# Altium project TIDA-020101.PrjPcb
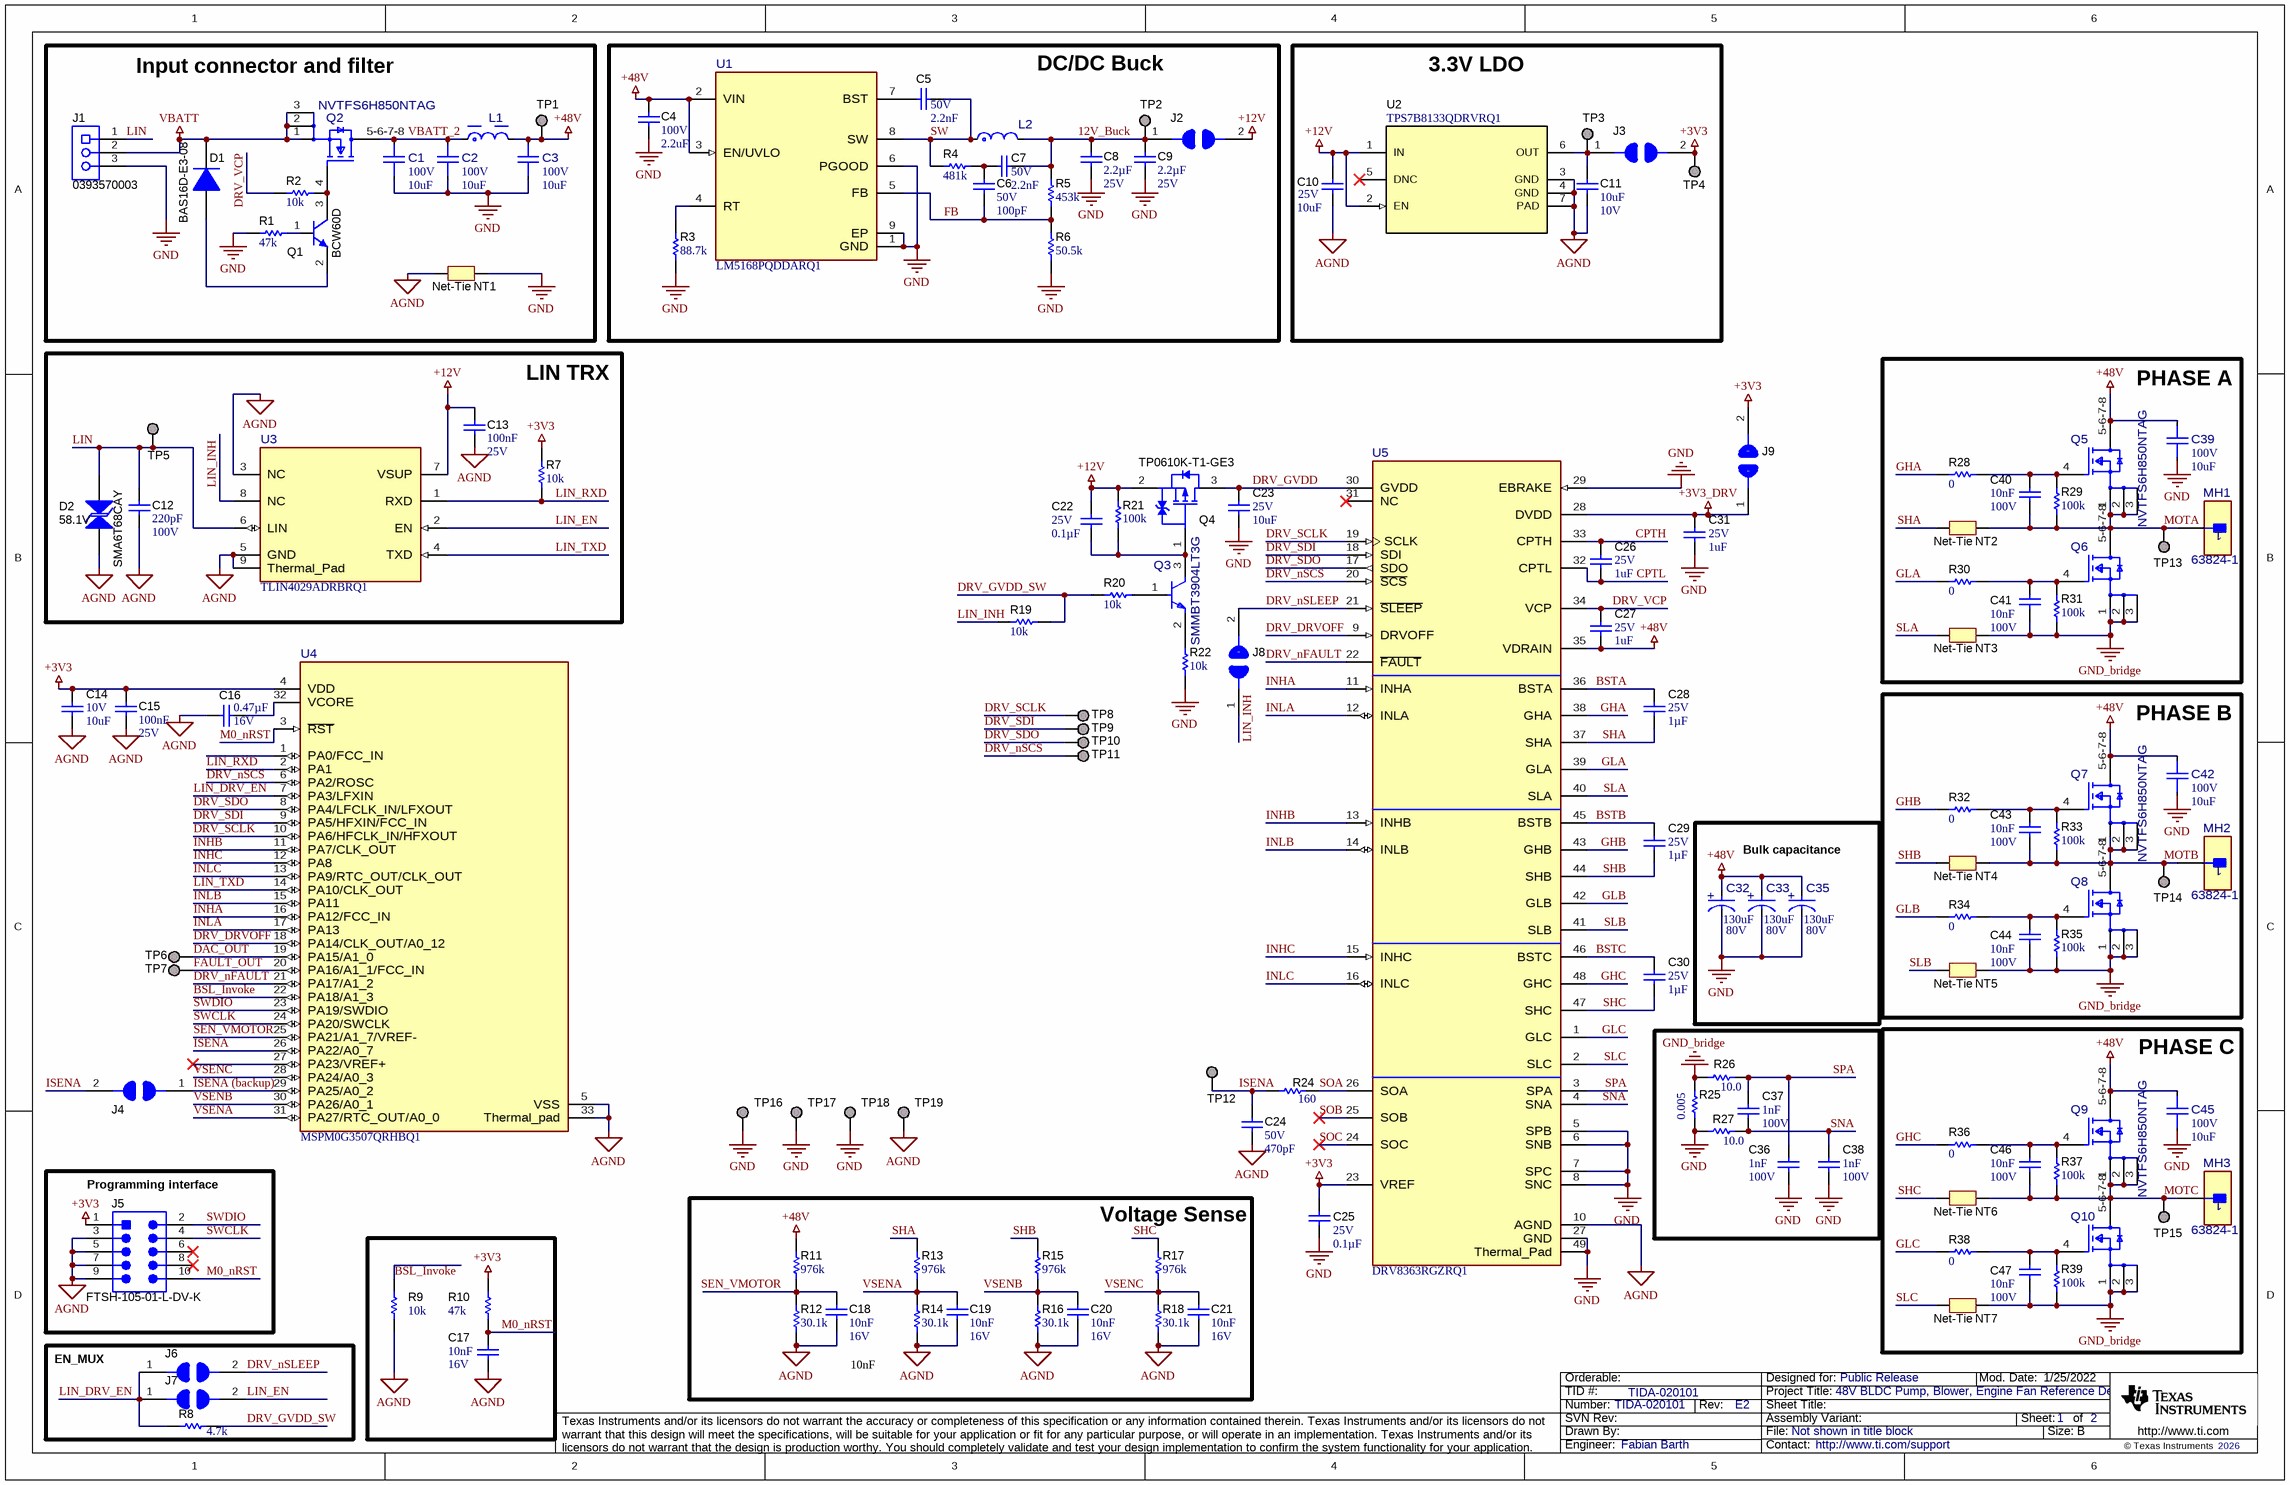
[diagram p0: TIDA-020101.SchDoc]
CopyrightYear: 2026; PCB_Layout: Fabian Barth; PCB_Rev: E2; PRJ_Customer: Public Release; PRJ_Engineer: Fabian Barth; PRJ_Number: TIDA-020101; PRJ_Title: 48V BLDC Pump, Blower, Engine Fan Reference Design; SCH_Rev: E2; TechSupport: http://www.ti.com/support; TID: TIDA-020101
2 sheets, 152 parts. Net scope: global (net labels, ports and power ports of the same name join across sheets).
Board file: TIDA-020101.PcbDoc
Sheets:
  TIDA-020101.SchDoc
  TIDA-020101_Hardware.SchDoc

## Sheet TIDA-020101.SchDoc
size 431 x 279 mm; Date: Not shown in title block; ApprovedBy: Not shown in title block; CheckedBy: Not shown in title block; Author: Not shown in title block; CompanyName: Not shown in title block; Engineer: Not shown in title block; Organization: Not shown in title block; Address1: Not shown in title block; Address2: Not shown in title block; Address3: Not shown in title block; Address4: Not shown in title block; DocumentNumber: 2; Revision: Use project parameter SCH_Rev; SheetNumber: 1; SheetTotal: 2; PageSetup: Record=PageOptions¦CenterHorizontal=True¦CenterVertical=True¦PrintScale=1.00¦XCorrection=1.00¦YCorrection=1.00¦PrintKind=0¦BorderSize=5000000¦LeftOffset=0¦BottomOffset=0¦Orientation=2¦PaperLength=1000¦PaperWidth=1000¦Scale=100¦PaperSource=15¦PrintQuality=600¦MediaType=1¦DitherType=10¦PaperKind=Letter¦PrintScaleMode=1

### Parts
C1  VDC_V: 100V  ValueDisplayed: 10uF  [FP-CGA6P1X7R2A106K250AC_1210-MFG]  (hidden comment: CGA6P1X7R2A106K250AC)
C2  VDC_V: 100V  ValueDisplayed: 10uF  [FP-CGA6P1X7R2A106K250AC_1210-MFG]  (hidden comment: CGA6P1X7R2A106K250AC)
C3  VDC_V: 100V  ValueDisplayed: 10uF  [FP-CGA6P1X7R2A106K250AC_1210-MFG]  (hidden comment: CGA6P1X7R2A106K250AC)
C4  VDC_V: 100V  ValueDisplayed: 2.2uF  [1210_250L]  (hidden comment: CGA6N3X7R2A225K230AB)
C5  Cap_F: 2.2nF  VDC_V: 50V  [0402S]  (hidden comment: CL05B222JB5NNNC)
C6  VDC_V: 50V  ValueDisplayed: 100pF  [0402L]  (hidden comment: CC0402KRX7R9BB101)
C7  Cap_F: 2.2nF  VDC_V: 50V  [0603L]  (hidden comment: GRM188R71H222KA01D)
C8  Cap_F: 2.2µF  VDC_V: 25V  [0805L]  (hidden comment: CGA4J3X7R1E225K125AB)
C9  Cap_F: 2.2µF  VDC_V: 25V  [0805L]  (hidden comment: CGA4J3X7R1E225K125AB)
C10  VDC_V: 25V  ValueDisplayed: 10uF  [0805L]  (hidden comment: GRM21BZ71E106KE15L)
C11  ValueDisplayed: 10uF  VDC_V: 10V  [0603L]  (hidden comment: GRM188Z71A106MA73D)
C12  Cap_F: 220pF  VDC_V: 100V  [0603L]  (hidden comment: GRM188R72A221KA01D)
C13  Cap_F: 100nF  VDC_V: 25V  [0402L]  (hidden comment: CGA2B3X7R1E104K050BB)
C14  VDC_V: 10V  ValueDisplayed: 10uF  [0603L]  (hidden comment: C1608X5R1A106M080AC)
C15  Cap_F: 100nF  VDC_V: 25V  [0402L]  (hidden comment: CGA2B3X7R1E104K050BB)
C16  ValueDisplayed: 0.47µF  VDC_V: 16V  [0402S]  (hidden comment: CGA2B1X7S1C474K050BE)
C17  Cap_F: 10nF  VDC_V: 16V  [0402S]  (hidden comment: GRM155R71C103KA01D)
C18  Cap_F: 10nF  VDC_V: 16V  [0402S]  (hidden comment: GRM155R71C103KA01D)
C19  Cap_F: 10nF  VDC_V: 16V  [0402S]  (hidden comment: GRM155R71C103KA01D)
C20  Cap_F: 10nF  VDC_V: 16V  [0402S]  (hidden comment: GRM155R71C103KA01D)
C21  Cap_F: 10nF  VDC_V: 16V  [0402S]  (hidden comment: GRM155R71C103KA01D)
C22  VDC_V: 25V  ValueDisplayed: 0.1µF  [0402L]  (hidden comment: CGA2B3X7R1E104K050BB)
C23  VDC_V: 25V  ValueDisplayed: 10uF  [0805L]  (hidden comment: GRM21BZ71E106KE15L)
C24  VDC_V: 50V  ValueDisplayed: 470pF  [0402L]  (hidden comment: CGA2B2X7R1H471K050BA)
C25  VDC_V: 25V  ValueDisplayed: 0.1µF  [0402L]  (hidden comment: CGA2B3X7R1E104K050BB)
C26  VDC_V: 25V  ValueDisplayed: 1uF  [0402S]  (hidden comment: C1005X5R1E105K050BC)
C27  VDC_V: 25V  ValueDisplayed: 1uF  [0402S]  (hidden comment: C1005X5R1E105K050BC)
C28  VDC_V: 25V  ValueDisplayed: 1µF  [0603S]  (hidden comment: CGA3E1X7R1E105K080AD)
C29  VDC_V: 25V  ValueDisplayed: 1µF  [0603S]  (hidden comment: CGA3E1X7R1E105K080AD)
C30  VDC_V: 25V  ValueDisplayed: 1µF  [0603S]  (hidden comment: CGA3E1X7R1E105K080AD)
C31  VDC_V: 25V  ValueDisplayed: 1uF  [0402L]  (hidden comment: C1005X5R1E105K050BC)
C32  ValueDisplayed: 130uF  VDC_V: 80V  [FP-B40910A0137M000_SMD2-MFG]  (hidden comment: B40910A0137M000)
C33  ValueDisplayed: 130uF  VDC_V: 80V  [FP-B40910A0137M000_SMD2-MFG]  (hidden comment: B40910A0137M000)
C35  ValueDisplayed: 130uF  VDC_V: 80V  [FP-B40910A0137M000_SMD2-MFG]  (hidden comment: B40910A0137M000)
C36  Cap_F: 1nF  VDC_V: 100V  [0402L]  (hidden comment: CGA2B3X7S2A102K050BB)
C37  Cap_F: 1nF  VDC_V: 100V  [0402L]  (hidden comment: CGA2B3X7S2A102K050BB)
C38  Cap_F: 1nF  VDC_V: 100V  [0402L]  (hidden comment: CGA2B3X7S2A102K050BB)
C39  VDC_V: 100V  ValueDisplayed: 10uF  [FP-CGA6P1X7R2A106K250AC_1210-MFG]  (hidden comment: CGA6P1X7R2A106K250AC)
C40  Cap_F: 10nF  VDC_V: 100V  [0603S]  (hidden comment: CGA3E2X7R2A103K080AA)
C41  Cap_F: 10nF  VDC_V: 100V  [0603S]  (hidden comment: CGA3E2X7R2A103K080AA)
C42  VDC_V: 100V  ValueDisplayed: 10uF  [FP-CGA6P1X7R2A106K250AC_1210-MFG]  (hidden comment: CGA6P1X7R2A106K250AC)
C43  Cap_F: 10nF  VDC_V: 100V  [0603S]  (hidden comment: CGA3E2X7R2A103K080AA)
C44  Cap_F: 10nF  VDC_V: 100V  [0603S]  (hidden comment: CGA3E2X7R2A103K080AA)
C45  VDC_V: 100V  ValueDisplayed: 10uF  [FP-CGA6P1X7R2A106K250AC_1210-MFG]  (hidden comment: CGA6P1X7R2A106K250AC)
C46  Cap_F: 10nF  VDC_V: 100V  [0603S]  (hidden comment: CGA3E2X7R2A103K080AA)
C47  Cap_F: 10nF  VDC_V: 100V  [0603S]  (hidden comment: CGA3E2X7R2A103K080AA)
D1  BAS16D-E3-08  [SOD-123]
D2  SMA6T68CAY  value 58.1V  [SMA_Bi]
J1  0393570003  [MOLEX_39357-0003]
J2  SOLDER JUMPER  [SolderJumper_50MIL]  (value not drawn)
J3  SOLDER JUMPER  [SolderJumper_50MIL]  (value not drawn)
J4  SOLDER JUMPER  [SolderJumper_50MIL]  (value not drawn)
J5  FTSH-105-01-L-DV-K  [Samtec_FTSH-105-01-x-DV-K]
J6  SOLDER JUMPER  [SolderJumper_50MIL]  (value not drawn)
J7  SOLDER JUMPER  [SolderJumper_50MIL]  (value not drawn)
J8  SOLDER JUMPER  [SolderJumper_50MIL]  (value not drawn)
J9  SOLDER JUMPER  [SolderJumper_50MIL]  (value not drawn)
L1  74438377022  [FP-74438377022_SMD2-MFG]  (value not drawn)
L2  LPS4040-104MRC  [FP-LPS4040-104MRC_SMT_IND_3MM9_3MM9-MFG]  (value not drawn)
MH1  63824-1  [FP-63824-1_CONN_7MM92_3MM11-MFG]
MH2  63824-1  [FP-63824-1_CONN_7MM92_3MM11-MFG]
MH3  63824-1  [FP-63824-1_CONN_7MM92_3MM11-MFG]
NT1  Net-Tie  [Net-Tie_50milWide_30milLong]  (net tie, no BOM)
NT2  Net-Tie  [Net-Tie_20milWide_60milLong]  (net tie, no BOM)
NT3  Net-Tie  [Net-Tie_20milWide_60milLong]  (net tie, no BOM)
NT4  Net-Tie  [Net-Tie_20milWide_60milLong]  (net tie, no BOM)
NT5  Net-Tie  [Net-Tie_20milWide_60milLong]  (net tie, no BOM)
NT6  Net-Tie  [Net-Tie_20milWide_60milLong]  (net tie, no BOM)
NT7  Net-Tie  [Net-Tie_20milWide_60milLong]  (net tie, no BOM)
Q1  BCW60D  [SOT-23]
Q2  NVTFS6H850NTAG  [FP-NVTFS6H850NTAG_WDFN8-MFG]
Q3  SMMBT3904LT3G  [FP-SMMBT3904LT3G_SOT23-IPC_C]
Q4  TP0610K-T1-GE3  [SOT-23L]
Q5  NVTFS6H850NTAG  [FP-NVTFS6H850NTAG_WDFN8-MFG]
Q6  NVTFS6H850NTAG  [FP-NVTFS6H850NTAG_WDFN8-MFG]  (value not drawn)
Q7  NVTFS6H850NTAG  [FP-NVTFS6H850NTAG_WDFN8-MFG]
Q8  NVTFS6H850NTAG  [FP-NVTFS6H850NTAG_WDFN8-MFG]  (value not drawn)
Q9  NVTFS6H850NTAG  [FP-NVTFS6H850NTAG_WDFN8-MFG]
Q10  NVTFS6H850NTAG  [FP-NVTFS6H850NTAG_WDFN8-MFG]  (value not drawn)
R1  ValueDisplayed: 47k  [0402L]  (hidden comment: CRCW040247K0JNED)
R2  ValueDisplayed: 10k  [0402L]  (hidden comment: CRCW040210K0JNED)
R3  ValueDisplayed: 88.7k  [0603L]  (hidden comment: CRCW060388K7FKEA)
R4  ValueDisplayed: 481k  [0603L]  (hidden comment: RT0603DRE07481KL)
R5  ValueDisplayed: 453k  [0603L]  (hidden comment: RC0603FR-07453KL)
R6  ValueDisplayed: 50.5k  [0603L]  (hidden comment: RT0603BRD0750K5L)
R7  ValueDisplayed: 10k  [0402L]  (hidden comment: CRCW040210K0JNED)
R8  ValueDisplayed: 4.7k  [0402L]  (hidden comment: CRCW04024K70JNED)
R9  ValueDisplayed: 10k  [0402L]  (hidden comment: CRCW040210K0JNED)
R10  ValueDisplayed: 47k  [0402L]  (hidden comment: CRCW040247K0JNED)
R11  ValueDisplayed: 976k  [0402S]  (hidden comment: CRCW0402976KFKED)
R12  ValueDisplayed: 30.1k  [0402S]  (hidden comment: CRCW040230K1FKED)
R13  ValueDisplayed: 976k  [0402S]  (hidden comment: CRCW0402976KFKED)
R14  ValueDisplayed: 30.1k  [0402S]  (hidden comment: CRCW040230K1FKED)
R15  ValueDisplayed: 976k  [0402S]  (hidden comment: CRCW0402976KFKED)
R16  ValueDisplayed: 30.1k  [0402S]  (hidden comment: CRCW040230K1FKED)
R17  ValueDisplayed: 976k  [0402S]  (hidden comment: CRCW0402976KFKED)
R18  ValueDisplayed: 30.1k  [0402S]  (hidden comment: CRCW040230K1FKED)
R19  ValueDisplayed: 10k  [0402L]  (hidden comment: CRCW040210K0JNED)
R20  ValueDisplayed: 10k  [0402L]  (hidden comment: CRCW040210K0JNED)
R21  ValueDisplayed: 100k  [0402L]  (hidden comment: CRCW0402100KJNED)
R22  ValueDisplayed: 10k  [0402L]  (hidden comment: CRCW040210K0JNED)
R24  ValueDisplayed: 160  [0402L]  (hidden comment: CRCW0402160RJNED)
R25  ValueDisplayed: 0.005  [CRE2512-R5_R9]  (hidden comment: CRE2512-FZ-R005E-3)
R26  ValueDisplayed: 10.0  [0402L]  (hidden comment: CRCW040210R0FKED)
R27  ValueDisplayed: 10.0  [0402L]  (hidden comment: CRCW040210R0FKED)
R28  ValueDisplayed: 0  [0402L]  (hidden comment: CRCW04020000Z0ED)
R29  ValueDisplayed: 100k  [0402S]  (hidden comment: CRCW0402100KJNED)
R30  ValueDisplayed: 0  [0402L]  (hidden comment: CRCW04020000Z0ED)
R31  ValueDisplayed: 100k  [0402S]  (hidden comment: CRCW0402100KJNED)
R32  ValueDisplayed: 0  [0402L]  (hidden comment: CRCW04020000Z0ED)
R33  ValueDisplayed: 100k  [0402S]  (hidden comment: CRCW0402100KJNED)
R34  ValueDisplayed: 0  [0402L]  (hidden comment: CRCW04020000Z0ED)
R35  ValueDisplayed: 100k  [0402S]  (hidden comment: CRCW0402100KJNED)
R36  ValueDisplayed: 0  [0402L]  (hidden comment: CRCW04020000Z0ED)
R37  ValueDisplayed: 100k  [0402S]  (hidden comment: CRCW0402100KJNED)
R38  ValueDisplayed: 0  [0402L]  (hidden comment: CRCW04020000Z0ED)
R39  ValueDisplayed: 100k  [0402S]  (hidden comment: CRCW0402100KJNED)
TP1  5017  [Keystone_5017]  (value not drawn)
TP2  5017  [Keystone_5017]  (value not drawn)
TP3  5017  [Keystone_5017]  (value not drawn)
TP4  5017  [Keystone_5017]  (value not drawn)
TP5  5017  [Keystone_5017]  (value not drawn)
TP6  5017  [Keystone_5017]  (value not drawn)
TP7  5017  [Keystone_5017]  (value not drawn)
TP8  5017  [Keystone_5017]  (value not drawn)
TP9  5017  [Keystone_5017]  (value not drawn)
TP10  5017  [Keystone_5017]  (value not drawn)
TP11  5017  [Keystone_5017]  (value not drawn)
TP12  5017  [Keystone_5017]  (value not drawn)
TP13  5017  [Keystone_5017]  (value not drawn)
TP14  5017  [Keystone_5017]  (value not drawn)
TP15  5017  [Keystone_5017]  (value not drawn)
TP16  5017  [Keystone_5017]  (value not drawn)
TP17  5017  [Keystone_5017]  (value not drawn)
TP18  5017  [Keystone_5017]  (value not drawn)
TP19  5017  [Keystone_5017]  (value not drawn)
U1  LM5168PQDDARQ1  [DDA0008E-IPC_C]
U2  TPS7B8133QDRVRQ1  [DRV0006A]
U3  TLIN4029ADRBRQ1  [DRB0008J-MFG]
U4  MSPM0G3507QRHBQ1  [RHB0032D-MFG]
U5  DRV8363RGZRQ1  [RGZ0048L-MFG]

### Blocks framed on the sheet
Input connector and filter: C1-C3 D1 J1 L1 NT1 Q1 Q2 R1 R2 TP1
DC/DC Buck: C4-C9 J2 L2 R3-R6 TP2 U1
3.3V LDO: C10 C11 J3 TP3 TP4 U2
LIN TRX: C12 C13 D2 R7 TP5 U3
PHASE A: C39-C41 MH1 NT2 NT3 Q5 Q6 R28-R31 TP13
PHASE B: C42-C44 MH2 NT4 NT5 Q7 Q8 R32-R35 TP14
Bulk capacitance: C32 C33 C35
PHASE C: C45-C47 MH3 NT6 NT7 Q9 Q10 R36-R39 TP15
Programming interface: J5
Voltage Sense: C18-C21 R11-R18
EN_MUX: J6 J7 R8

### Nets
+3V3: C14.1 C15.1 C25.1 J3.2 J5.1 J9.2 R7.2 R10.2 TP4.1 U4.4(VDD) U5.23(VREF)
+3V3_DRV: C31.1 J9.1 U5.28(DVDD)
+12V: C10.1 C13.1 C22.1 J2.2 Q4.2(S) R21.2 U2.1(IN) U2.2(EN) U3.7(VSUP)
+48V: C3.2 C4.1 C27.2 C32.2(ANODE) C33.2(ANODE) C35.2(ANODE) C39.2 C42.2 C45.2 L1.2 Q5.5-6-7-8(D) Q7.5-6-7-8(D) Q9.5-6-7-8(D) R11.2 TP1.1 U1.2(VIN) U1.3(EN/UVLO) U5.35(VDRAIN)
AGND: C10.2 C11.2 C12.2 C13.2 C14.2 C15.2 C16.1 C17.2 C18.2 C19.2 C20.2 C21.2 C24.2 D2.1 J5.3 J5.5 J5.7 J5.9 NT1.1 R9.1 R12.1 R14.1 R16.1 R18.1 TP19.1 U2.3(GND) U2.4(GND) U2.7(PAD) U3.3(NC) U3.5(GND) U3.9(Thermal_Pad) U4.5(VSS) U4.33(Thermal_pad) U5.10(AGND)
GND: C1.1 C2.1 C3.1 C4.2 C8.2 C9.2 C23.2 C25.2 C31.2 C32.1(CATHODE) C33.1(CATHODE) C35.1(CATHODE) C36.2 C38.2 C39.1 C42.1 C45.1 J1.3 NT1.2 R1.1 R3.1 R6.1 R22.2 R25.1 R27.1 TP16.1 TP17.1 TP18.1 U1.1(GND) U1.6(PGOOD) U1.9(EP) U5.5(SPB) U5.6(SNB) U5.7(SPC) U5.8(SNC) U5.27(GND) U5.29(EBRAKE) U5.49(Thermal_Pad)
GND_bridge: C41.2 C44.2 C47.2 NT3.2 NT5.2 NT7.2 Q6.1(S) Q6.2(S) Q6.3(S) Q8.1(S) Q8.2(S) Q8.3(S) Q10.1(S) Q10.2(S) Q10.3(S) R25.2 R26.1 R31.1 R35.1 R39.1
VBATT: D1.1(K) J1.2 Q2.1(S) Q2.2(S) Q2.3(S)
12V_Buck: C7.1 C8.1 C9.1 J2.1 L2.2 R5.2 TP2.1
BSL_Invoke: R9.2 U4.22(PA18/A1_3)
BSTA: C28.1 U5.36(BSTA)
BSTB: C29.1 U5.45(BSTB)
BSTC: C30.1 U5.46(BSTC)
CPTH: C26.1 U5.33(CPTH)
CPTL: C26.2 U5.32(CPTL)
DAC_OUT: TP6.1 U4.19(PA15/A1_0)
DRV_DRVOFF: U4.18(PA14/CLK_OUT/A0_12) U5.9(DRVOFF)
DRV_GVDD: C23.1 Q4.3(D) U5.30(GVDD)
DRV_GVDD_SW: R8.2 R19.1 R20.2
DRV_nFAULT: U4.21(PA17/A1_2) U5.22(~{FAULT})
DRV_nSCS: TP11.1 U4.6(PA2/ROSC) U5.20(~{SCS})
DRV_nSLEEP: J6.2 J8.2 U5.21(~{SLEEP})
DRV_SCLK: TP8.1 U4.10(PA6/HFCLK_IN/HFXOUT) U5.19(SCLK)
DRV_SDI: TP9.1 U4.9(PA5/HFXIN/FCC_IN) U5.18(SDI)
DRV_SDO: TP10.1 U4.8(PA4/LFCLK_IN/LFXOUT) U5.17(SDO)
DRV_VCP: C27.1 R2.2 U5.34(VCP)
FAULT_OUT: TP7.1 U4.20(PA16/A1_1/FCC_IN)
FB: C6.1 R5.1 R6.2 U1.5(FB)
GHA: R28.1 U5.38(GHA)
GHB: R32.1 U5.43(GHB)
GHC: R36.1 U5.48(GHC)
GLA: R30.1 U5.39(GLA)
GLB: R34.1 U5.42(GLB)
GLC: R38.1 U5.1(GLC)
INHA: U4.16(PA12/FCC_IN) U5.11(INHA)
INHB: U4.11(PA7/CLK_OUT) U5.13(INHB)
INHC: U4.12(PA8) U5.15(INHC)
INLA: U4.17(PA13) U5.12(INLA)
INLB: U4.15(PA11) U5.14(INLB)
INLC: U4.13(PA9/RTC_OUT/CLK_OUT) U5.16(INLC)
ISENA: C24.1 J4.2 R24.1 TP12.1 U4.26(PA22/A0_7)
ISENA (backup): J4.1 U4.29(PA25/A0_2)
LIN: C12.1 D2.2 J1.1 TP5.1 U3.6(LIN)
LIN_DRV_EN: J6.1 J7.1 R8.1 U4.7(PA3/LFXIN)
LIN_EN: J7.2 U3.2(EN)
LIN_INH: J8.1 R19.2 U3.8(NC)
LIN_RXD: R7.1 U3.1(RXD) U4.2(PA1)
LIN_TXD: U3.4(TXD) U4.14(PA10/CLK_OUT)
M0_nRST: C17.1 J5.10 R10.1 U4.3(~{RST})
MOTA: C40.2 MH1.1 NT2.2 Q5.1(S) Q5.2(S) Q5.3(S) Q6.5-6-7-8(D) R29.1 TP13.1
MOTB: C43.2 MH2.1 NT4.2 Q7.1(S) Q7.2(S) Q7.3(S) Q8.5-6-7-8(D) R33.1 TP14.1
MOTC: C46.2 MH3.1 NT6.2 Q9.1(S) Q9.2(S) Q9.3(S) Q10.5-6-7-8(D) R37.1 TP15.1
SEN_VMOTOR: C18.1 R11.1 R12.2 U4.25(PA21/A1_7/VREF-)
SHA: C28.2 NT2.1 R13.2 U5.37(SHA)
SHB: C29.2 NT4.1 R15.2 U5.44(SHB)
SHC: C30.2 NT6.1 R17.2 U5.47(SHC)
SLA: NT3.1 U5.40(SLA)
SLB: NT5.1 U5.41(SLB)
SLC: NT7.1 U5.2(SLC)
SNA: C37.2 C38.1 R27.2 U5.4(SNA)
SOA: R24.2 U5.26(SOA)
SOB: U5.25(SOB)
SOC: U5.24(SOC)
SPA: C36.1 C37.1 R26.2 U5.3(SPA)
SW: C5.1 L2.1 R4.1 U1.8(SW)
SWCLK: J5.4 U4.24(PA20/SWCLK)
SWDIO: J5.2 U4.23(PA19/SWDIO)
VBATT_2: C1.2 C2.2 L1.1 Q2.5-6-7-8(D)
VSENA: C19.1 R13.1 R14.2 U4.31(PA27/RTC_OUT/A0_0)
VSENB: C20.1 R15.1 R16.2 U4.30(PA26/A0_1)
VSENC: C21.1 R17.1 R18.2 U4.28(PA24/A0_3)
NetC5_2: C5.2 U1.7(BST)
NetC6_2: C6.2 C7.2 R4.2
NetC11_1: C11.1 J3.1 TP3.1 U2.6(OUT)
NetC16_2: C16.2 U4.32(VCORE)
NetC22_2: C22.2 Q3.3(COLLECTOR) Q4.1(G) R21.1
NetC40_1: C40.1 Q5.4(G) R28.2 R29.2
NetC41_1: C41.1 Q6.4(G) R30.2 R31.2
NetC43_1: C43.1 Q7.4(G) R32.2 R33.2
NetC44_1: C44.1 Q8.4(G) R34.2 R35.2
NetC46_1: C46.1 Q9.4(G) R36.2 R37.2
NetC47_1: C47.1 Q10.4(G) R38.2 R39.2
NetD1_2: D1.2(A) Q1.2(E)
NetQ1_1: Q1.1(B) R1.2
NetQ1_3: Q1.3(C) Q2.4(G) R2.1
NetQ3_1: Q3.1(BASE) R20.1
NetQ3_2: Q3.2(EMITTER) R22.1
NetR3_2: R3.2 U1.4(RT)

Not connected (* = marked no-connect by the designer): J5 6* 8*; U2 5(DNC)*; U4 1(PA0/FCC_IN) 27(PA23/VREF+)*; U5 31(NC)*

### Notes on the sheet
- 10nF

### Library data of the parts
C1-C3 C39 C42 C45 = CMP-0125410-1: 10 µF ±10% 100V Ceramic Capacitor X7R 1210 (3225 Metric); Manufacturer: TDK; TempCo: 15%; Value: 10µF; SizeZ_mm: 2.8mm; AEC Qualified: Yes; AEC Grade: Grade 1
C4 = CMP-0009152-2: CAP, CERM, 2.2 uF, 100 V, +/- 10%, X7R, AEC-Q200 Grade 1,; Manufacturer: TDK; TaMin_C: -55°C; ESR_ohm: 1.73m; Polarized: N; SizeAreaWB_mm2: 14.7; Value1: 0.00173 ohm; U/M: EA; Value: 2.2uF; TaMax_C: 125°C; SizeZ_mm: 2.5; SizeX_mm: 3.2; Cap_Case: 1210_250; SizeArea_mm2: 8; AEC Qualified: Y; Cap_F: 2.2µF; IRMS_A: 5.59317A; AEC Grade: 1; AEC Category: Q200
C5 = CMP-0006344-2: CAP, CERM, 2200 pF, 50 V, +/- 5%, X7R, 0402; Manufacturer: Samsung Electro-Mechanics; TaMin_C: -55°C; Polarized: N; SizeAreaWB_mm2: 3; Value1: Unknown; U/M: EA; Value: 2200pF; TaMax_C: 125°C; SizeZ_mm: 0.6; SizeX_mm: 1; SizeY_mm: 0.5; Cap_Case: 0402; AEC Category: Q200
C6 = CMP-0006305-2: CAP, CERM, 100 pF, 50 V, +/- 10%, X7R, 0402; Manufacturer: Yageo America; TaMin_C: -55°C; Polarized: N; SizeAreaWB_mm2: 3; Value1: Unknown; U/M: EA; Value: 100pF; TaMax_C: 125°C; SizeZ_mm: 0.6; SizeX_mm: 1; SizeY_mm: 0.5; Cap_Case: 0402; AEC Category: Q200
C7 = CMP-0007443-4: CAP, CERM, 2200 pF, 50 V, +/- 10%, X7R, 0603; Manufacturer: MuRata; TaMin_C: -55°C; Polarized: N; SizeAreaWB_mm2: 4.68; Value1: Unknown; U/M: EA; Value: 2200pF; TaMax_C: 125°C; SizeZ_mm: 1; SizeX_mm: 1.6; SizeY_mm: 0.8; Cap_Case: 0603; SizeArea_mm2: 1.28; AEC Category: Q200
C8 C9 = CMP-0007975-2: CAP, CERM, 2.2 uF, 25 V, +/- 10%, X7R, AEC-Q200 Grade 1, 0805; Manufacturer: TDK; TaMin_C: -55°C; Polarized: N; SizeAreaWB_mm2: 6.75; Value1: Unknown; U/M: EA; Value: 2.2uF; TaMax_C: 125°C; SizeZ_mm: 1.45; SizeX_mm: 2; SizeY_mm: 1.25; Cap_Case: 0805; SizeArea_mm2: 2.5; AEC Qualified: Y; AEC Grade: 1; AEC Category: Q200
C10 C23 = CMP-0008378-2: CAP, CERM, 10 uF, 25 V, +/- 10%, X7R, 0805; Manufacturer: MuRata; TaMin_C: -55°C; Polarized: N; SizeAreaWB_mm2: 6.75; Value1: Unknown; U/M: EA; Value: 10uF; TaMax_C: 125°C; SizeZ_mm: 1.45; SizeX_mm: 2; SizeY_mm: 1.25; Cap_Case: 0805; SizeArea_mm2: 2.5; Cap_F: 10µF; AEC Category: Q200
C11 = CMP-0007497-5: CAP, CERM, 10 uF, 10 V, +/- 20%, X7R, 0603; Manufacturer: MuRata; Value: 10uF; SizeY_mm: 0.8; TaMin_C: -55°C; SizeAreaWB_mm2: 4.68; SizeX_mm: 1.6; U/M: EA; SizeZ_mm: 1; Cap_Case: 0603; Cap_F: 10µF; Value1: Unknown; AEC Category: Q200; AEC Qualified: N; TaMax_C: 125°C; SizeArea_mm2: 1.28
C12 = CMP-0007474-4: CAP, CERM, 220 pF, 100 V, +/- 10%, X7R, 0603; Manufacturer: MuRata; TaMin_C: -55°C; Polarized: N; SizeAreaWB_mm2: 4.68; Value1: Unknown; U/M: EA; Value: 220pF; TaMax_C: 125°C; SizeZ_mm: 1; SizeX_mm: 1.6; SizeY_mm: 0.8; Cap_Case: 0603; SizeArea_mm2: 1.28; AEC Category: Q200
C13 C15 = CMP-0080610-1: CAP, CERM, 0.1 µF, 25 V,+/- 10%, X7R, AEC-Q200 Grade 1, 0402; Manufacturer: TDK; TaMin_C: -55°C; Polarized: N; SizeAreaWB_mm2: 3; U/M: EA; Value: 0.1uF; TaMax_C: 125°C; SizeZ_mm: 0.6; SizeX_mm: 1; SizeY_mm: 0.5; Cap_Case: 0402; AEC Qualified: Y; AEC Category: Q200; ValueDisplayed: 0.1µF
C14 = CMP-0007003-5: CAP, CERM, 10 uF, 10 V, +/- 20%, X5R, 0603; Manufacturer: TDK; TaMin_C: -55°C; Polarized: N; SizeAreaWB_mm2: 4.68; Value1: 0.0078 ohm; U/M: EA; Value: 10uF; TaMax_C: 85°C; SizeZ_mm: 1; SizeX_mm: 1.6; SizeY_mm: 0.8; Cap_Case: 0603; SizeArea_mm2: 1.28; Cap_F: 10µF; AEC Category: Q200; ESR_ohm: 7.8m; IRMS_A: 1.85A
C16 = CMP-0860964-1: CAP, CERM, 0.47 µF, 16 V,+/- 10%, X7S, 0402; Manufacturer: TDK; Value: 0.47uF; SizeY_mm: 0.5; TaMin_C: -55°C; SizeAreaWB_mm2: 3; SizeX_mm: 1; U/M: EA; SizeZ_mm: 0.6; Cap_Case: 0402; Cap_F: 470nF; AEC Category: Q200; Polarized: N; TaMax_C: 125°C
C17-C21 = CMP-0006639-2: CAP, CERM, 0.01 uF, 16 V, +/- 10%, X7R, 0402; Manufacturer: MuRata; TaMin_C: -55°C; Polarized: N; SizeAreaWB_mm2: 3; Value1: Unknown; U/M: EA; Value: 0.01uF; TaMax_C: 125°C; SizeZ_mm: 0.6; SizeX_mm: 1; SizeY_mm: 0.5; Cap_Case: 0402; AEC Category: Q200
C22 C25 = CMP-0080610-1: CAP, CERM, 0.1 µF, 25 V,+/- 10%, X7R, AEC-Q200 Grade 1, 0402; Manufacturer: TDK; TaMin_C: -55°C; Polarized: N; SizeAreaWB_mm2: 3; U/M: EA; Value: 0.1uF; TaMax_C: 125°C; SizeZ_mm: 0.6; SizeX_mm: 1; SizeY_mm: 0.5; Cap_Case: 0402; AEC Qualified: Y; Cap_F: 100nF; AEC Category: Q200
C24 = CMP-0006320-2: CAP, CERM, 470 pF, 50 V, +/- 10%, X7R, AEC-Q200 Grade 1, 0402; Manufacturer: TDK; TaMin_C: -55°C; ESR_ohm: 4.96489; Polarized: N; SizeAreaWB_mm2: 3; Value1: 4.96489 ohm; U/M: EA; Value: 470pF; TaMax_C: 125°C; SizeZ_mm: 0.6; SizeX_mm: 1; SizeY_mm: 0.5; Cap_Case: 0402; AEC Qualified: Y; IRMS_A: 2.28414dA; AEC Category: Q200
C26 C27 C31 = CMP-0006276-2: CAP, CERM, 1 uF, 25 V, +/- 10%, X5R, 0402; Manufacturer: TDK; TaMin_C: -55°C; Polarized: N; SizeAreaWB_mm2: 3; Value1: Unknown; U/M: EA; Value: 1uF; TaMax_C: 80°C; SizeZ_mm: 0.6; SizeX_mm: 1; SizeY_mm: 0.5; Cap_Case: 0402; Cap_F: 1µF; AEC Category: Q200
C28-C30 = CMP-0082523-1: CAP, CERM, 1 µF, 25 V,+/- 10%, X7R, AEC-Q200 Grade 1, 0603; Manufacturer: TDK; TaMin_C: -55°C; Polarized: N; SizeAreaWB_mm2: 4.68; U/M: EA; Value: 1uF; TaMax_C: 125°C; SizeZ_mm: 1; SizeX_mm: 1.6; SizeY_mm: 0.8; Cap_Case: 0603; SizeArea_mm2: 1.28; AEC Qualified: Y; AEC Category: Q200
C32 C33 C35 = CMP-0127119-1: 130 µF 80 V Aluminum - Polymer Capacitors Radial, Can - SMD 16mOhm 4000 Hrs @ 125°C; Manufacturer: TDK; AEC Qualified: Yes; Cap_F: 130µF; IRMS_A: 4.1A; SizeZ_mm: 16.8mm; Tolerance_%: 20%; Dissipation Factor: 8%; Esr: 16m; Leakage Current: 100uA; Life: 4000Hours; Value: 130µF; AEC Grade: Grade 0; TaMax_C: 150°C; TaMin_C: -55°C
C36-C38 = CMP-0006332-2: CAP, CERM, 1000 pF, 100 V, +/- 10%, X7S, AEC-Q200 Grade 1, 0402; Manufacturer: TDK; TaMin_C: -55°C; ESR_ohm: 2.7115; Polarized: N; SizeAreaWB_mm2: 3; Value1: 2.71151 ohm; U/M: EA; Value: 1000pF; TaMax_C: 125°C; SizeZ_mm: 0.6; SizeX_mm: 1; SizeY_mm: 0.5; Cap_Case: 0402; AEC Qualified: Y; IRMS_A: 264.589mA; AEC Category: Q200
C40 C41 C43 C44 C46 C47 = CMP-0007082-4: CAP, CERM, 0.01 uF, 100 V, +/- 10%, X7R, AEC-Q200 Grade 1, 0603; Manufacturer: TDK; TaMin_C: -55°C; ESR_ohm: 0.2354; Polarized: N; SizeAreaWB_mm2: 4.68; Value1: 0.235428 ohm; U/M: EA; Value: 0.01uF; TaMax_C: 125°C; SizeZ_mm: 1; SizeX_mm: 1.6; SizeY_mm: 0.8; Cap_Case: 0603; SizeArea_mm2: 1.28; AEC Qualified: Y; IRMS_A: 396.995mA; AEC Category: Q200
D1 = CMP-0080761-2: Diode, Switching, 100 V, 0.25 A, AEC-Q101, SOD-123; Manufacturer: Vishay-Semiconductor; SizeArea_mm2: 6.545; Io_A: 250mA; TJmax_C: 150°C; SizeY_mm: 1.7; Value1: 0.25A; Value: 100V; Vf_V: 1.25V; SizeAreaWB_mm2: 13.095; AEC Category: Q101; SizeX_mm: 3.85; SizeZ_mm: 1.35; AEC Qualified: Y
D2 = CMP-0006043-3: Diode, TVS, Bi, 58.1 V, 121 Vc, AEC-Q101, SMD, 2-Leads, Body 4.275x2.575mm; Manufacturer: STMicroelectronics; Ppk: 600W; Ipp: 33A; AEC Qualified: Y; SizeX_mm: 5.075; Vc: 121V; SizeZ_mm: 2.65; Vbr_Max: 71.4V; SizeY_mm: 2.575; AEC Category: Q101; SizeAreaWB_mm2: 32.368125; SizeArea_mm2: 13.068125; Vbr_Min: 64.6V
J1 = CMP-0055340-2: Terminal Block, 3.5 mm, 3x1, Tin, TH; Manufacturer: Molex; CNHeader: FALSE; CT: TRUE; Green_REACh: Incomplete; Green_Lifecycle: Not Set
J2-J4 J6-J9 = CMP-0080367-2: Solder Jumper, SMT; Manufacturer: NA
J5 = CMP-0075634-2: Header(Shrouded), 1.27mm, 5x2, Gold, SMT; Manufacturer: Samtec; Pitch_mm: 1.27; Gender: Male; Cert_CSA: Y; Current_A: 3.3A; Row_Count: 2
L1 = CMP-0126669-1: 2.2 µH Shielded Wirewound Inductor 12.4 A 11.9mOhm Max Nonstandard; Manufacturer: Wurth Electronics; Isat: 6.5A; Irms: 12.4A; DCR_ohm: 11.9m; Material: Iron Alloy; Value: 2.2uH; SizeZ_mm: 3.1mm; Ind_H: 2.2µH; AEC Qualified: Yes; AEC Grade: Grade 1; Self Resonant Frequency: 30MHz; Shrouded: true; TaMax_C: +85°C; TaMin_C: -40°C; Test Frequency: 100kHz; Tolerance_%: 20%
L2 = CMP-0123992-1: Low Profile Shielded Power Inductors 100uH 20% 0.82A 0.475 Ohm; Manufacturer: Coilcraft; Isat: 0.35A; DCR_ohm: 0.475; Material: Ferrite; SizeZ_mm: 4.15mm; Ind_H: 100µH; AEC Qualified: Yes; AEC Grade: Grade 1; Self Resonant Frequency: 8.6MHz; Shrouded: true; TaMax_C: +125°C; TaMin_C: -40°C; Test Frequency: 100kHz
MH1-MH3 = CMP-0089624-1: 0.250" (6.35mm) Quick Connect Male  Solder Connector Non-Insulated; Manufacturer: TE Connectivity; SizeZ_mm: 10.71mm; Conn Orientation: Straight; AEC Qualified: No; Import Ts: 1521847382; ContactFinish: Tin,Nickel; Current_A: 20A; Ciiva Ids: 766930
NT1-NT7 = CMP-0078142-6: Single point connection between nets.
Q1 = CMP-0000380-2: Transistor, NPN, 32 V, 0.1 A, SOT-23; Manufacturer: Infineon Technologies; TaMax_C: 150°C; Value2: 630; Value1: 0.1 A; Vcesat1_V: 1.2dV; SizeX_mm: 2.5; SizeY_mm: 3; TaMin_C: -65°C; IcRated_A: 1dA; CompType: BJT; SizeZ_mm: 1.1; Value: 32 V; SizeArea_mm2: 7.5; NPN: 1; Vceo_V: 32V; PNP: 0; AEC Category: Q101; SizeAreaWB_mm2: 14; U/M: EA
Q2 Q5-Q10 = CMP-0126680-2: N-Channel 80 V 11A (Ta), 68A (Tc) 3.2W (Ta), 107W (Tc) Surface Mount 8-WDFN (3.3x3.3); Manufacturer: onsemi; VdsMax_V: 1.2V; Input Capacitace At Vds: 1140pF @ 40V; Pulse Drain Current: 300A; Rthja Max: 47°C/W; Standoff Height: 0mm; ChMode: False; Number Of Channels: 1; AEC Qualified: No; Rdson45_ohm: 8.5m; Threshold Vgs Max: 4V; Reverse Recovery Time: 40ns; Turn On Delay Time: 11ns; Typ Forward Diode Voltage: 0.8V; Threshold Vgs Min: 2V; Drain To Source Breakdown Voltage: 80V; Reverse Recovery Charge: 40nC; SizeZ_mm: 0.8mm; TJmax_C: +175°C; Turn Off Delay Time: 34ns; Vgs_V: 20V; QgTyp_nC: 19nC @ 10V; Transconductance: 63S
Q3 = CMP-0097440-1: Bipolar (BJT) Transistor NPN 40 V 200 mA 300MHz 300 mW Surface Mount SOT-23-3 (TO-236); Manufacturer: On Semiconductor; Vcesat1_V: 300mV; IcRated_A: 200mA; SizeZ_mm: 1.11mm; AEC Qualified: Yes; Value: 40V; NPN: 1; AEC Grade: Grade 0; Collector Base Voltage: 60V; Emitter Base Voltage: 6V; Hfe Min: 100; Hfe Testic: 10mA; Hfe Testvce: 1V; Power_W: 225mW; Rthja Max: 556°C/W; TJmax_C: +150°C; Hfe Max: 300; Import Ts: 1521847306; Hfe Ss Testvce: 10V; Ciiva Ids: 19584013; Hfe Ss Testic: 1mA; Hfe Ss Max: 400; Standoff Height: 0.01mm; Rise Time Tr: 35ns; Fall Time Tf: 50ns
Q4 = CMP-0000155-3: MOSFET, P-CH, -60 V, -0.185 A, SOT-23; Manufacturer: Vishay-Siliconix; Alternate Manufacturer: None; AEC Category: Q101; IdsMax_A: -185mA; ChMode: Enhancement; SizeX_mm: 2.5; Value: -60V; Rdson45_ohm: 10; SizeY_mm: 3; Value1: 1; Value2: 1.7 nC; Vgs_V: -20V; SizeZ_mm: 1.1; ChType: P; SizeAreaWB_mm2: 14; SizeArea_mm2: 7.5; QgTyp_nC: 1.7
R1 R10 = CMP-0026935-3: RES, 47 k, 5%, 0.063 W, AEC-Q200 Grade 0, 0402; Manufacturer: Vishay-Dale; Power_W: 63mW; TempCo: 200 ppm/C; Value_Code: 47k0; Value: 47k; EIA_Code: E24; SizeX_mm: 1; SizeY_mm: 0.5; SizeZ_mm: 0.6; Value2: 0.063W; AEC Qualified: Y; VDC_V: 50V; AEC Category: Q200; AEC Grade: 0
R2 R7 R9 R19 R20 R22 = CMP-0026825-5: RES, 10 k, 5%, 0.063 W, AEC-Q200 Grade 0, 0402; Manufacturer: Vishay-Dale; Power_W: 63mW; TempCo: 200 ppm/C; Value_Code: 10k0; Value: 10k; EIA_Code: E24; SizeX_mm: 1; SizeY_mm: 0.5; SizeZ_mm: 0.6; Value2: 0.063W; AEC Qualified: Y; VDC_V: 50V; AEC Category: Q200; AEC Grade: 0
R3 = CMP-0022632-4: RES, 88.7 k, 1%, 0.1 W, AEC-Q200 Grade 0, 0603; Manufacturer: Vishay-Dale; Power_W: 100mW; TempCo: 100 ppm/C; Value_Code: 88k7; Value: 88.7k; EIA_Code: E96; SizeX_mm: 1.6; SizeY_mm: 0.8; SizeZ_mm: 1; Value2: 0.1W; SizeArea_mm2: 1.28; AEC Qualified: Y; VDC_V: 75V; AEC Category: Q200; AEC Grade: 0
R4 = CMP-0025319-2: RES, 481 k, 0.5%, 0.1 W, 0603; Manufacturer: Yageo America; Power_W: 100mW; TempCo: 50 ppm/C; Value: 481k; EIA_Code: E192; SizeX_mm: 1.6; SizeY_mm: 0.8; SizeZ_mm: 1; Value2: 0.1W; SizeArea_mm2: 1.28; VDC_V: 75V; AEC Category: Q200; U/M: EA
R5 = CMP-0023120-4: RES, 453 k, 1%, 0.1 W, 0603; Manufacturer: Yageo; Power_W: 100mW; TempCo: 100 ppm/C; Value: 453k; EIA_Code: E96; SizeX_mm: 1.6; SizeY_mm: 0.8; SizeZ_mm: 1; Value2: 0.1W; SizeArea_mm2: 1.28; AEC Qualified: N; VDC_V: 75V; AEC Category: Q200; SizeAreaWB_mm2: 4.68
R6 = CMP-0024307-2: RES, 50.5 k, 0.1%, 0.1 W, 0603; Manufacturer: Yageo America; Power_W: 100mW; TempCo: 25 ppm/C; Value_Code: 50k5; U/M: EA; Value: 50.5k; EIA_Code: E192; SizeX_mm: 1.6; SizeY_mm: 0.8; SizeZ_mm: 1; Value2: 0.1W; SizeArea_mm2: 1.28; VDC_V: 75V; AEC Category: Q200
R8 = CMP-0026938-5: RES, 4.7 k, 5%, 0.063 W, AEC-Q200 Grade 0, 0402; Manufacturer: Vishay-Dale; Power_W: 63mW; TempCo: 200 ppm/C; Value_Code: 4k70; Value: 4.7k; EIA_Code: E24; SizeX_mm: 1; SizeY_mm: 0.5; SizeZ_mm: 0.6; Value2: 0.063W; AEC Qualified: Y; VDC_V: 50V; AEC Category: Q200; AEC Grade: 0
R11 R13 R15 R17 = CMP-0026615-3: RES, 976 k, 1%, 0.063 W, AEC-Q200 Grade 0, 0402; Manufacturer: Vishay-Dale; Power_W: 63mW; TempCo: 100 ppm/C; Value: 976k; EIA_Code: E96; SizeX_mm: 1; SizeY_mm: 0.5; SizeZ_mm: 0.6; Value2: 0.063W; AEC Qualified: Y; VDC_V: 50V; AEC Category: Q200; AEC Grade: 0
R12 R14 R16 R18 = CMP-0026284-2: RES, 30.1 k, 1%, 0.063 W, AEC-Q200 Grade 0, 0402; Manufacturer: Vishay-Dale; Power_W: 63mW; TempCo: 100 ppm/C; Value_Code: 30k1; Value: 30.1k; EIA_Code: E96; SizeX_mm: 1; SizeY_mm: 0.5; SizeZ_mm: 0.6; Value2: 0.063W; AEC Qualified: Y; VDC_V: 50V; AEC Category: Q200; AEC Grade: 0
R21 R29 R31 R33 R35 R37 R39 = CMP-0026823-3: RES, 100 k, 5%, 0.063 W, AEC-Q200 Grade 0, 0402; Manufacturer: Vishay-Dale; Power_W: 63mW; TempCo: 200 ppm/C; Value: 100k; EIA_Code: E24; SizeX_mm: 1; SizeY_mm: 0.5; SizeZ_mm: 0.6; Value2: 0.063W; AEC Qualified: Y; VDC_V: 50V; AEC Category: Q200; AEC Grade: 0
R24 = CMP-0026845-3: RES, 160, 5%, 0.063 W, AEC-Q200 Grade 0, 0402; Manufacturer: Vishay-Dale; Power_W: 63mW; TempCo: 200 ppm/C; Value_Code: 160R; Value: 160; EIA_Code: E24; SizeX_mm: 1; SizeY_mm: 0.5; SizeZ_mm: 0.6; Value2: 0.063W; AEC Qualified: Y; VDC_V: 50V; AEC Category: Q200; AEC Grade: 0
R25 = CMP-0015751-2: RES, 0.005, 1%, 3 W, AEC-Q200 Grade 0, 2512; Manufacturer: Bourns; Power_W: 3W; TempCo: 75 ppm/C; Value_Code: 5L000; U/M: EA; Value: 0.005; EIA_Code: E96; Res_ohm: 5m; SizeX_mm: 6.45; SizeY_mm: 3.35; SizeZ_mm: 0.9; SizeArea_mm2: 21.6075; AEC Qualified: Y; AEC Grade: 0; AEC Category: Q200
R26 R27 = CMP-0025963-3: RES, 10.0, 1%, 0.063 W, AEC-Q200 Grade 0, 0402; Manufacturer: Vishay-Dale; VDC_V: 50V; AEC Grade: 0; AEC Qualified: Y; TempCo: 100 ppm/C; Res_ohm: 10; SizeZ_mm: 0.6; Power_W: 63mW; Value: 10.0; Value_Code: 10R0; EIA_Code: E96; SizeX_mm: 1; SizeY_mm: 0.5; Value2: 0.063W; AEC Category: Q200
R28 R30 R32 R34 R36 R38 = CMP-0026822-3: RES, 0, 5%, 0.063 W, AEC-Q200 Grade 0, 0402; Manufacturer: Vishay-Dale; Power_W: 63mW; TempCo: 200 ppm/C; Value_Code: 0000; Value: 0; EIA_Code: E24; SizeX_mm: 1; SizeY_mm: 0.5; SizeZ_mm: 0.6; Value2: 0.063W; AEC Qualified: Y; VDC_V: 50V; AEC Category: Q200
TP1-TP19 = CMP-0078225-3: PC Test Point, SMT; Manufacturer: Keystone Electronics
U1 = CMP-0092718-1: 0.3-A,120-V, Step-Down Converter with Fly-buck Capability; Manufacturer: Texas Instruments; Max Supply Voltage: 115V; SizeZ_mm: 1.7mm; Switching Frequency: 1MHz; Max Duty Cycle: 100%; Number Of Outputs: 1; Nominal Supply Current: 10-420uA; Min Supply Voltage: 6V; Standoff Height: 0mm; AEC Qualified: Yes; Output Type: AdjustableProgrammable; Switching Topology: Buck; TJmax_C: +150°C
U2 = CMP-0860463-2: Automotive 150-mA high-voltage ultra-low-IQ low-dropout (LDO) linear regulator, DRV0006A (WSON-6); Manufacturer: Texas Instruments; AEC Category: Q200; AEC Qualified: Y; CompType: IC; SizeAreaWB_mm2: 9; SizeArea_mm2: 4; SizeX_mm: 2; SizeZ_mm: 0.8
U3 = CMP-0126781-1: Automotive LIN Transceiver with Dominant State Timeout and Extended Fault Protection; Manufacturer: Texas Instruments; TJmax_C: +150°C; TaMax_C: +125°C; SizeZ_mm: 1mm; Nominal Supply Current: 1-1.2mA; Min Supply Voltage: 4V; Standoff Height: 0mm; TaMin_C: -40°C; AEC Qualified: Yes; Max Supply Voltage: 48V; AEC Grade: Grade 1
U4 = CMP-0120871-1: Automotive Mixed-Signal Microcontrollers With CAN-FD Interface; Manufacturer: Texas Instruments; SizeZ_mm: 1mm; AEC Qualified: Yes; AEC Grade: Grade 1; Core Architecture: ARM Cortex-M0+; Data Bus Width: 32bits; Frequency_Fixed: 80MHz; Interface: I2C,SPI,UART,CAN,LIN,IrDA,SMBus,Other; Max Supply Voltage: 3.6V; Memory Size: 128KBytes; Memory Type: FLASH; Min Supply Voltage: 1.62V; Number Of A/D Converters: 2; Number Of Adc Channels: 11; Number Of Cores: 1; Number Of I/Os: 28; Number Of Pwm Channels: 22; Number Of Timers/Counters: 7; Number Of Uart Channels: 4; Ram Size: 32KBytes; Standoff Height: 0mm; TaMax_C: +125°C; TaMin_C: -40°C; TJmax_C: +130°C
U5 = CMP-0122985-1: 48V Battery Three-Phase Smart Gate Driver with Accurate Current Sensing and Advanced Monitoring; Manufacturer: Texas Instruments; SizeZ_mm: 1mm; AEC Qualified: Yes; AEC Grade: Grade 1; Max Supply Voltage: 85V; Min Supply Voltage: 8V; Number Of Drivers: 3; Propagation Delay: 42ns; Standoff Height: 0mm; TaMax_C: +125°C; TaMin_C: -40°C; TJmax_C: +150°C

## Sheet TIDA-020101_Hardware.SchDoc
size 431 x 279 mm; Date: Not shown in title block; ApprovedBy: Not shown in title block; CheckedBy: Not shown in title block; Author: Not shown in title block; CompanyName: Not shown in title block; Engineer: Not shown in title block; Organization: Not shown in title block; Address1: Not shown in title block; Address2: Not shown in title block; Address3: Not shown in title block; Address4: Not shown in title block; DocumentNumber: 3; Revision: Use project parameter SCH_Rev; SheetNumber: 2; SheetTotal: 2; PageSetup: Record=PageOptions¦CenterHorizontal=True¦CenterVertical=True¦PrintScale=1.00¦XCorrection=1.00¦YCorrection=1.00¦PrintKind=0¦BorderSize=5000000¦LeftOffset=0¦BottomOffset=0¦Orientation=2¦PaperLength=1000¦PaperWidth=1000¦Scale=100¦PaperSource=15¦PrintQuality=600¦MediaType=1¦DitherType=10¦PaperKind=Letter¦PrintScaleMode=1
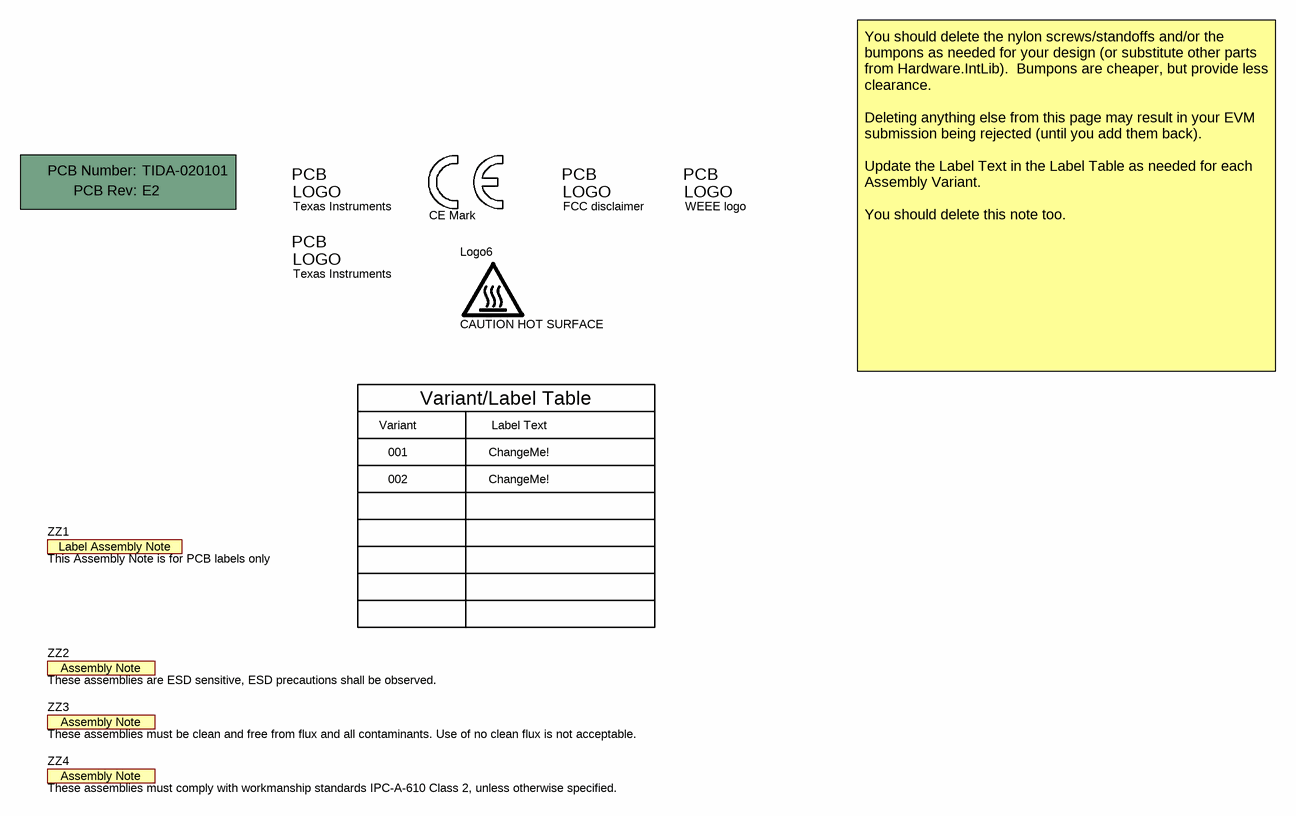
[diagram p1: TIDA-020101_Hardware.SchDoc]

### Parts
!PCB1  Printed Circuit Board  (value not drawn)  (mechanical)
Logo1  CE Mark  [CE_Mark_5mm]  (no BOM)
Logo2  Texas Instruments  [TI_Stacked_Overlay_Small]  (no BOM)
Logo3  FCC disclaimer  [FCC_disclaimer]  (no BOM)
Logo4  WEEE logo  [WEEE_Minimum]  (no BOM)
Logo5  Texas Instruments  [TI_Symbol_Overlay_Small]  (no BOM)
Logo6  CAUTION HOT SURFACE  [IEC_HotSurface_Small]  (no BOM)
ZZ1  This Assembly Note is for PCB labels only  [AssemblyNoteLabel]  (no BOM)
ZZ2  These assemblies are ESD sensitive, ESD precautions shall be observed.  [AssemblyNote]  (no BOM)
ZZ3  These assemblies must be clean and free from flux and all contaminants. Use of no clean flux is not acceptable.  [AssemblyNote]  (no BOM)
ZZ4  These assemblies must comply with workmanship standards IPC-A-610 Class 2, unless otherwise specified.  [AssemblyNote]  (no BOM)

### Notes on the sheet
- Variant
- Variant/Label Table
- Label Text
- You should delete the nylon screws/standoffs and/or the bumpons as needed for your design (or substitute other parts from Hardware.IntLib).  Bumpons are cheaper, but provide less clearance.
  Deleting anything else from this page may result in your EVM submission being rejected (until you add them back).
  Update the Label Text in the Label Table as needed for each Assembly Variant.
  You should delete this note too.
- 001
- 002
- ChangeMe!

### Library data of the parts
!PCB1 = CMP-0003618-2: Manufacturer: Any; PartNumber: TIDA-020101
Logo1 = CMP-0074844-1: SymbolCreator: a0412235
Logo2 Logo5 = CMP-0074838-1: Texas Instrument Corporate Signature; SymbolCreator: a0412235; Lib Reference: TI_Logo; Library Reference: Logo
Logo3 = CMP-0074847-1: FCC_disclaimer; Library Reference: Logo
Logo4 = CMP-0074769-1
Logo6 = CMP-0074837-2: IEC 61010-1 Hot Surface Warning; Manufacturer: Texas Instruments; CompType: IC; AEC Category: Q200; SymbolCreator: a0412235
ZZ1 = CMP-0003616-3
ZZ2 = CMP-0077236-1
ZZ3 = CMP-0077237-1
ZZ4 = CMP-0077238-1

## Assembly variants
TLIN4029A-Q1: not fitted C35 C47 J7 J9 R10
TLIN2021A-Q1: not fitted C10 C11 C35 C47 J3 R41 U2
